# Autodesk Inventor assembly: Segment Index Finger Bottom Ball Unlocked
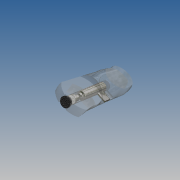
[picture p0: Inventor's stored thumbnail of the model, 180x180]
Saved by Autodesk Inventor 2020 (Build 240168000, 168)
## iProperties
Created: 2019-10
Part Number: Segment Index Finger Bottom Ball Unlocked
Document SubType Name: Assembly
Designer: yello
Author: yello
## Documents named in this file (7)
- C:\Users\yello\Documents\Mechanical Hand\Prototype 2 (Realistic Hand)\Segment Index Finger Bottom Ball Unlocked.iam
- C:\Users\yello\Documents\Mechanical Hand\Prototype 2 (Realistic Hand)\Segment Index Finger Bottom.ipt
- C:\Users\yello\Documents\Mechanical Hand\Prototype 2 (Realistic Hand)\Push Part.ipt
- C:\Users\yello\Documents\Mechanical Hand\Prototype 2 (Realistic Hand)\Plug.ipt
- C:\Users\yello\Documents\Mechanical Hand\Prototype 2 (Realistic Hand)\Ball.ipt
- C:\Users\yello\Documents\Mechanical Hand\Prototype 2 (Realistic Hand)\Spring 2.ipt
- C:\Users\yello\Documents\Mechanical Hand\Prototype 2 (Realistic Hand)\Lock.ipt
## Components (7 placed, 6 different names)
1. Segment Index Finger Bottom:1 — Mate:1, Mate:2, Mate:3, Mate:6, Mate:7, Mate:11
2. Push Part:1 — Mate:1, Mate:8, Mate:9, Mate:10
3. Plug:1 — Mate:2, Mate:3
4. Ball:1 — Mate:6
5. Ball:2 — Mate:7
6. Spring 2:1 — Mate:8
7. Lock:1 — Mate:9, Mate:10, Mate:11
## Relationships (9: Mate 9)
- Mate:1: Segment Index Finger Bottom:1 ↔ Push Part:1
- Mate:2: Segment Index Finger Bottom:1 ↔ Plug:1
- Mate:3: Segment Index Finger Bottom:1 ↔ Plug:1
- Mate:6: Segment Index Finger Bottom:1 ↔ Ball:1
- Mate:7: Segment Index Finger Bottom:1 ↔ Ball:2
- Mate:8: Push Part:1 ↔ Spring 2:1
- Mate:9: Push Part:1 ↔ Lock:1
- Mate:10: Push Part:1 ↔ Lock:1
- Mate:11: Segment Index Finger Bottom:1 ↔ Lock:1
